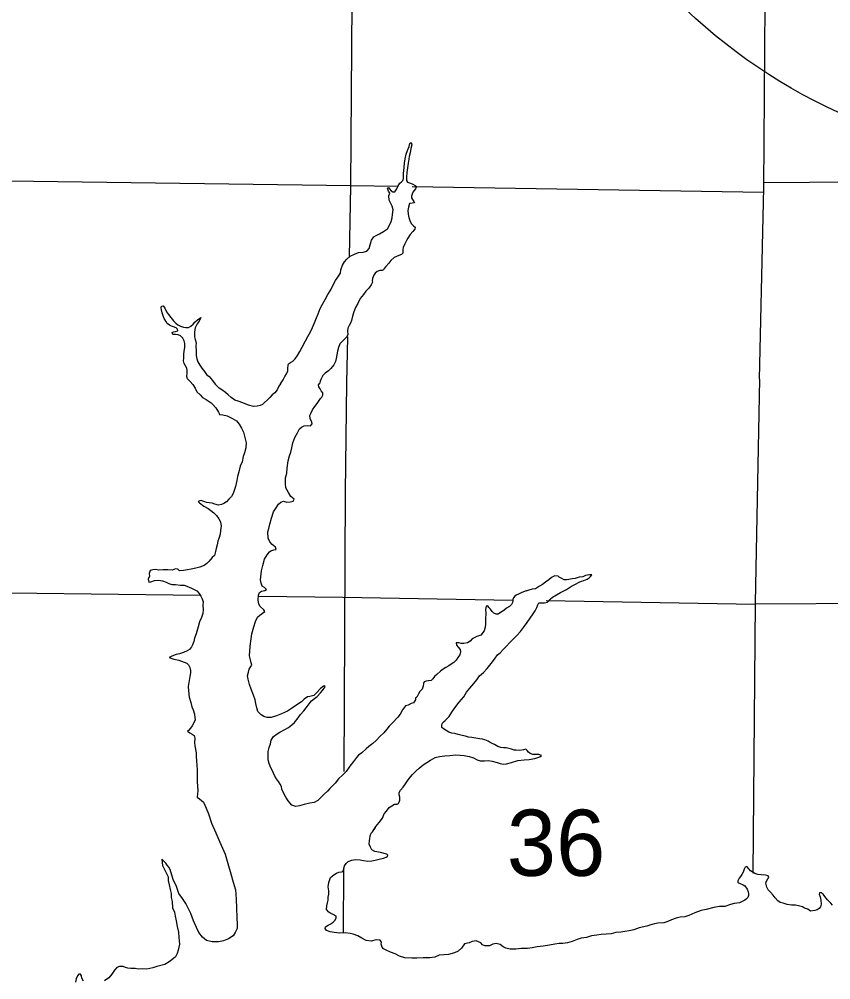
# Model space of a CAD drawing. Extents: x 77230 to 630905, y 790554 to 1662844.
# Drawn here: x 282531 to 292892, y 1585968 to 1598238 of the extents above; entities that cross this region are included whole.
import ezdxf

# ---------------------------------------------------------------- set-up
doc = ezdxf.new("R2010")
doc.units = 0
for name, color, linetype in [('Level 15', 7, 'Continuous'), ('Level 16', 7, 'Continuous'), ('Level 17', 7, 'Continuous'), ('Level 41', 7, 'Continuous')]:
    doc.layers.add(name, color=color, linetype=linetype)

msp = doc.modelspace()

# ---------------------------------------------------------------- linework, layer by layer
at = {"layer": 'Level 15'}
for points in [[(291982, 1593642), (292037, 1596088), (292076, 1601381), (292123, 1606664), (292223, 1611995), (292277, 1617183), (292295, 1618324)], [(291982, 1593642), (291925, 1590782), (291897, 1587331)]]:
    msp.add_lwpolyline(points, dxfattribs=at)
at = {"layer": 'Level 16'}
for points in [[(286981, 1617573), (286974, 1617268), (286950, 1611933), (286885, 1606684), (286800, 1601404), (286761, 1596105), (286743, 1595204)], [(267582, 1596443), (270927, 1596351), (276202, 1596266), (281460, 1596188), (286763, 1596113), (287364, 1596104)], [(292039, 1596154), (294372, 1596171)], [(287547, 1596101), (292034, 1596030)], [(286722, 1594182), (286711, 1593588)], [(286711, 1593588), (286693, 1592200), (286676, 1588627)], [(284846, 1590876), (281357, 1590920), (276135, 1591001), (276103, 1591002)], [(288831, 1590814), (286663, 1590853), (285588, 1590866)], [(291925, 1590760), (289256, 1590807)], [(291925, 1590806), (291929, 1590806)], [(291925, 1590770), (296585, 1590797), (298273, 1590778)], [(286671, 1587398), (286667, 1586565)]]:
    msp.add_lwpolyline(points, dxfattribs=at)
at = {"layer": 'Level 17'}
for points in [[(285866, 1593582), (285900, 1593632), (285923, 1593675), (285941, 1593707), (285959, 1593747), (285962, 1593781), (285964, 1593813), (285970, 1593837), (285992, 1593851), (286023, 1593870), (286053, 1593900), (286085, 1593944), (286114, 1593992), (286142, 1594047), (286187, 1594129), (286216, 1594187), (286248, 1594246), (286277, 1594302), (286301, 1594358), (286324, 1594423), (286348, 1594475), (286371, 1594543), (286399, 1594591), (286438, 1594658), (286471, 1594720), (286507, 1594780), (286540, 1594847), (286568, 1594899), (286599, 1594945), (286631, 1594996), (286638, 1595036), (286656, 1595098), (286683, 1595138), (286715, 1595174), (286755, 1595209), (286810, 1595237), (286864, 1595256), (286922, 1595264), (286970, 1595277), (286997, 1595311), (287011, 1595357), (287030, 1595417), (287058, 1595456), (287088, 1595476), (287129, 1595498), (287181, 1595527), (287231, 1595561), (287256, 1595609), (287278, 1595656), (287291, 1595700), (287297, 1595744), (287305, 1595802), (287294, 1595848), (287276, 1595884), (287254, 1595927), (287251, 1595980), (287263, 1596016), (287245, 1596041), (287232, 1596079), (287244, 1596087), (287260, 1596070), (287281, 1596044), (287301, 1596032), (287325, 1596032), (287352, 1596072), (287364, 1596103), (287389, 1596145), (287411, 1596161), (287429, 1596177), (287437, 1596205), (287438, 1596267), (287444, 1596343), (287451, 1596399), (287459, 1596456), (287472, 1596514), (287488, 1596562), (287507, 1596614), (287517, 1596650), (287535, 1596662), (287541, 1596632), (287531, 1596586), (287520, 1596532), (287508, 1596484), (287503, 1596450), (287497, 1596400), (287488, 1596340), (287480, 1596278), (287473, 1596222), (287475, 1596178), (287489, 1596156), (287527, 1596144), (287557, 1596132), (287587, 1596115), (287601, 1596099), (287590, 1596073), (287572, 1596052), (287556, 1596028), (287546, 1596004), (287537, 1595978), (287539, 1595956), (287553, 1595936)], [(287553, 1595936), (287567, 1595910), (287577, 1595894), (287547, 1595888), (287515, 1595884), (287502, 1595838), (287494, 1595796), (287495, 1595746), (287503, 1595704), (287519, 1595668), (287536, 1595630), (287566, 1595598), (287584, 1595580), (287582, 1595556), (287554, 1595528), (287521, 1595486), (287491, 1595441), (287474, 1595413), (287452, 1595369), (287434, 1595321), (287427, 1595295), (287429, 1595271), (287429, 1595251), (287411, 1595231), (287377, 1595218), (287346, 1595208), (287316, 1595192), (287276, 1595155), (287248, 1595123), (287211, 1595081), (287189, 1595054), (287181, 1595038), (287165, 1595026), (287135, 1595030), (287102, 1595014), (287076, 1594995), (287058, 1594967), (287040, 1594927), (287037, 1594897), (287039, 1594879), (287023, 1594847), (286994, 1594803), (286954, 1594766), (286926, 1594722), (286885, 1594670), (286852, 1594607), (286824, 1594555), (286803, 1594501), (286785, 1594445), (286772, 1594390), (286760, 1594354), (286742, 1594326), (286725, 1594292), (286723, 1594254), (286725, 1594210), (286715, 1594180), (286686, 1594156), (286656, 1594127), (286622, 1594091), (286605, 1594045), (286593, 1593997), (286584, 1593949), (286578, 1593905), (286570, 1593864), (286547, 1593824), (286509, 1593778), (286480, 1593746), (286438, 1593717), (286408, 1593685), (286385, 1593645), (286371, 1593615), (286367, 1593588)], [(284746, 1593572), (284712, 1593610), (284680, 1593644), (284672, 1593672), (284673, 1593716), (284673, 1593752), (284671, 1593782), (284653, 1593811), (284638, 1593841), (284630, 1593873), (284632, 1593907), (284631, 1593961), (284637, 1593999), (284643, 1594043), (284644, 1594094), (284636, 1594131), (284618, 1594163), (284591, 1594193), (284561, 1594207), (284527, 1594211), (284491, 1594210), (284485, 1594234), (284501, 1594246), (284525, 1594249), (284555, 1594257), (284551, 1594277), (284535, 1594297), (284501, 1594308), (284475, 1594316), (284448, 1594330), (284420, 1594352), (284404, 1594382), (284382, 1594413), (284370, 1594447), (284357, 1594489), (284349, 1594525), (284343, 1594551), (284349, 1594571), (284367, 1594575), (284391, 1594549), (284409, 1594502), (284435, 1594466), (284468, 1594426), (284500, 1594386), (284530, 1594357), (284556, 1594335), (284590, 1594317), (284628, 1594303), (284660, 1594300), (284690, 1594302), (284722, 1594316), (284750, 1594343), (284776, 1594373), (284805, 1594399), (284849, 1594427), (284829, 1594381), (284804, 1594345), (284776, 1594295), (284772, 1594275), (284767, 1594237), (284769, 1594179), (284777, 1594147), (284788, 1594105), (284786, 1594061), (284791, 1594005), (284791, 1593941), (284797, 1593901), (284812, 1593861), (284838, 1593819), (284862, 1593781), (284895, 1593738), (284923, 1593698), (284955, 1593674), (284977, 1593648), (284999, 1593622), (285032, 1593577)], [(284746, 1593572), (284775, 1593525), (284797, 1593477), (284839, 1593441), (284871, 1593407), (284917, 1593381), (284981, 1593339), (284999, 1593319), (285041, 1593273), (285055, 1593254), (285061, 1593238), (285075, 1593220), (285083, 1593202), (285087, 1593188), (285129, 1593184), (285185, 1593170), (285247, 1593140), (285305, 1593106), (285337, 1593067), (285369, 1593015), (285392, 1592965), (285410, 1592897), (285430, 1592825), (285426, 1592761), (285406, 1592697), (285390, 1592651), (285377, 1592585), (285353, 1592528), (285335, 1592456), (285319, 1592398), (285307, 1592346), (285292, 1592268), (285274, 1592216)], [(285866, 1593582), (285847, 1593549), (285823, 1593505), (285794, 1593465), (285760, 1593440), (285732, 1593406), (285700, 1593374), (285658, 1593336), (285638, 1593318), (285606, 1593302), (285568, 1593296), (285522, 1593293), (285458, 1593307), (285384, 1593337), (285326, 1593357), (285284, 1593372), (285236, 1593406), (285198, 1593442), (285164, 1593468), (285118, 1593502), (285084, 1593524), (285058, 1593550), (285032, 1593577)], [(285696, 1591395), (285726, 1591435), (285744, 1591449), (285780, 1591458), (285810, 1591464), (285801, 1591496), (285761, 1591528), (285731, 1591561), (285711, 1591611), (285703, 1591691), (285717, 1591733), (285731, 1591790), (285750, 1591864), (285778, 1591944), (285812, 1591998), (285842, 1592044), (285870, 1592068), (285904, 1592080), (285948, 1592071), (285992, 1592075), (286030, 1592081), (286039, 1592109), (285999, 1592143), (285967, 1592191), (285935, 1592253), (285931, 1592305), (285931, 1592379), (285947, 1592439), (285952, 1592503), (285966, 1592599), (285982, 1592661), (286000, 1592709), (286013, 1592763), (286025, 1592825), (286051, 1592897), (286083, 1592953), (286111, 1593004), (286135, 1593026), (286170, 1593044), (286216, 1593048), (286250, 1593044), (286270, 1593068), (286266, 1593090), (286246, 1593136), (286240, 1593176), (286256, 1593212), (286276, 1593250), (286306, 1593290), (286335, 1593329), (286379, 1593393), (286393, 1593411), (286407, 1593437), (286407, 1593467), (286387, 1593489), (286371, 1593515), (286357, 1593541), (286353, 1593569), (286367, 1593588)], [(285274, 1592216), (285262, 1592178), (285240, 1592140), (285208, 1592106), (285178, 1592074), (285145, 1592051), (285115, 1592039), (285075, 1592031), (285027, 1592043), (284993, 1592055), (284957, 1592059), (284923, 1592065), (284899, 1592074), (284877, 1592082), (284853, 1592092), (284835, 1592086), (284815, 1592078), (284833, 1592060), (284889, 1592016), (284941, 1591989), (284979, 1591963), (285017, 1591933), (285049, 1591899), (285079, 1591857), (285099, 1591817), (285109, 1591761), (285100, 1591707), (285098, 1591659), (285078, 1591605), (285066, 1591569), (285056, 1591523), (285044, 1591477), (285038, 1591437), (285023, 1591389), (284993, 1591361), (284955, 1591314), (284925, 1591286), (284891, 1591260), (284835, 1591238), (284787, 1591224), (284727, 1591211), (284678, 1591205), (284630, 1591195), (284578, 1591191), (284554, 1591211), (284526, 1591217), (284482, 1591200), (284426, 1591206), (284368, 1591204), (284310, 1591202), (284274, 1591208), (284236, 1591203), (284202, 1591197), (284190, 1591159), (284192, 1591125), (284178, 1591087), (284187, 1591045), (284213, 1591051), (284256, 1591068), (284308, 1591072), (284360, 1591062), (284406, 1591048), (284440, 1591028), (284478, 1591016), (284528, 1591017), (284588, 1591009), (284638, 1591009), (284694, 1590987), (284740, 1590965), (284800, 1590936), (284828, 1590902), (284850, 1590868), (284868, 1590836), (284881, 1590796), (284877, 1590752), (284879, 1590700), (284873, 1590646), (284857, 1590596), (284833, 1590542), (284814, 1590475), (284788, 1590387), (284768, 1590331), (284760, 1590291), (284742, 1590247), (284730, 1590219), (284703, 1590189), (284677, 1590169), (284629, 1590147), (284577, 1590132), (284533, 1590122), (284479, 1590102), (284445, 1590086), (284505, 1590064), (284567, 1590050), (284635, 1590027), (284669, 1590011), (284693, 1589993), (284709, 1589959), (284719, 1589919), (284717, 1589891), (284708, 1589843)], [(286109, 1588192), (286061, 1588181), (286013, 1588197), (285963, 1588255), (285933, 1588301), (285903, 1588355), (285885, 1588403), (285879, 1588435), (285864, 1588465), (285842, 1588499), (285816, 1588533), (285794, 1588569), (285778, 1588608), (285760, 1588644), (285738, 1588684), (285720, 1588732), (285708, 1588776), (285708, 1588830), (285709, 1588886), (285721, 1588934), (285739, 1588984), (285749, 1589029), (285777, 1589075), (285823, 1589109), (285860, 1589131), (285922, 1589165), (285968, 1589191), (286010, 1589224), (286044, 1589256), (286090, 1589314), (286122, 1589356), (286163, 1589402), (286195, 1589442), (286231, 1589495), (286261, 1589533), (286299, 1589561), (286335, 1589587), (286376, 1589633), (286402, 1589663), (286424, 1589693), (286436, 1589709), (286434, 1589725), (286414, 1589717), (286378, 1589687), (286328, 1589635), (286291, 1589599), (286243, 1589585), (286211, 1589583), (286167, 1589552), (286135, 1589518), (286075, 1589480), (286021, 1589442), (285954, 1589401), (285880, 1589367), (285814, 1589341), (285748, 1589317), (285696, 1589318), (285654, 1589332), (285618, 1589352), (285576, 1589394), (285564, 1589444), (285552, 1589496), (285542, 1589544), (285521, 1589604), (285491, 1589682), (285471, 1589742), (285453, 1589808), (285447, 1589850), (285457, 1589898), (285465, 1589934), (285486, 1589968), (285500, 1589986), (285492, 1590016), (285482, 1590054), (285470, 1590104), (285480, 1590230), (285493, 1590322), (285501, 1590386), (285527, 1590478), (285547, 1590544), (285574, 1590598), (285602, 1590625), (285638, 1590653), (285666, 1590671), (285654, 1590695), (285606, 1590737), (285590, 1590767), (285580, 1590823), (285584, 1590879), (285597, 1590913), (285625, 1590933), (285665, 1590939), (285687, 1590955), (285663, 1590979), (285633, 1590997), (285621, 1591033), (285611, 1591077), (285625, 1591191), (285640, 1591259), (285662, 1591339), (285696, 1591395)], [(288372, 1589801), (288406, 1589851), (288457, 1589893), (288503, 1589944), (288541, 1589988), (288573, 1590028), (288607, 1590078), (288637, 1590118), (288670, 1590146), (288708, 1590189), (288746, 1590225), (288794, 1590275), (288834, 1590313), (288882, 1590367), (288931, 1590418), (288969, 1590466), (289017, 1590530), (289055, 1590586), (289094, 1590642), (289118, 1590680), (289140, 1590722), (289152, 1590757), (289166, 1590781), (289200, 1590783), (289238, 1590783), (289276, 1590793), (289310, 1590829), (289340, 1590857), (289441, 1590914), (289519, 1590952), (289581, 1590998), (289633, 1591022), (289679, 1591045), (289709, 1591061), (289741, 1591069), (289782, 1591087), (289806, 1591103), (289826, 1591119), (289840, 1591139), (289810, 1591139), (289762, 1591133), (289726, 1591117), (289680, 1591111), (289629, 1591096), (289589, 1591088), (289549, 1591082), (289519, 1591076), (289489, 1591076), (289457, 1591096), (289425, 1591110), (289411, 1591124), (289367, 1591127), (289327, 1591107), (289293, 1591077), (289249, 1591047), (289213, 1591019), (289173, 1590995), (289149, 1590979), (289121, 1590964), (289078, 1590958), (289038, 1590946), (288998, 1590934)], [(288998, 1590934), (289004, 1590936), (288946, 1590916), (288904, 1590892), (288874, 1590883), (288856, 1590869), (288840, 1590847), (288832, 1590827), (288832, 1590809), (288830, 1590787), (288814, 1590761), (288789, 1590737), (288753, 1590713), (288717, 1590685), (288677, 1590661), (288647, 1590640), (288619, 1590640), (288591, 1590650), (288567, 1590674), (288547, 1590704), (288527, 1590722), (288515, 1590744), (288491, 1590742), (288485, 1590700), (288489, 1590646), (288483, 1590578), (288482, 1590512), (288478, 1590474), (288466, 1590424), (288424, 1590372), (288374, 1590351), (288338, 1590337), (288312, 1590325), (288288, 1590295), (288254, 1590271), (288205, 1590263), (288173, 1590264), (288143, 1590272), (288109, 1590272), (288113, 1590244), (288133, 1590218), (288159, 1590186), (288165, 1590156), (288155, 1590120), (288131, 1590086), (288107, 1590052), (288079, 1590022), (288046, 1589998), (288014, 1589980), (287976, 1589956), (287942, 1589937), (287908, 1589909), (287862, 1589869), (287832, 1589841), (287810, 1589813), (287788, 1589791), (287758, 1589787), (287727, 1589783), (287701, 1589776), (287693, 1589754), (287689, 1589720), (287673, 1589680), (287647, 1589650), (287629, 1589622), (287605, 1589580), (287589, 1589566), (287591, 1589542), (287564, 1589506), (287536, 1589496), (287498, 1589478), (287464, 1589469), (287426, 1589417), (287394, 1589363), (287364, 1589321), (287297, 1589251), (287253, 1589208), (287223, 1589170), (287187, 1589124), (287139, 1589078), (287087, 1589026), (287046, 1588988), (286996, 1588947), (286960, 1588917), (286904, 1588867), (286864, 1588837), (286838, 1588809), (286799, 1588757), (286753, 1588696), (286703, 1588630), (286663, 1588588), (286609, 1588534), (286564, 1588481), (286498, 1588413), (286468, 1588379), (286424, 1588339), (286378, 1588293), (286343, 1588259), (286297, 1588234), (286243, 1588224), (286169, 1588206), (286109, 1588192)], [(284708, 1589843), (284702, 1589793), (284688, 1589715), (284694, 1589661), (284702, 1589579), (284721, 1589511), (284735, 1589455), (284751, 1589415), (284769, 1589359), (284773, 1589317), (284775, 1589287), (284761, 1589249), (284739, 1589213), (284716, 1589183), (284690, 1589152), (284680, 1589142), (284708, 1589122), (284740, 1589107), (284764, 1589087), (284772, 1589055), (284768, 1588999), (284774, 1588955), (284788, 1588867), (284791, 1588819), (284793, 1588767), (284797, 1588705), (284803, 1588655), (284801, 1588601), (284803, 1588545), (284803, 1588495), (284806, 1588443), (284810, 1588385), (284806, 1588343), (284802, 1588301), (284832, 1588279), (284882, 1588235), (284916, 1588161), (284947, 1588087), (284987, 1587967), (285039, 1587847), (285091, 1587725), (285158, 1587572), (285194, 1587452), (285233, 1587322), (285263, 1587216), (285291, 1587118), (285299, 1586998), (285306, 1586882), (285310, 1586764), (285314, 1586674), (285313, 1586622), (285289, 1586572), (285263, 1586530), (285203, 1586493), (285137, 1586467), (285073, 1586453), (284995, 1586451), (284921, 1586472), (284869, 1586512), (284825, 1586572), (284795, 1586636), (284757, 1586720), (284721, 1586814), (284690, 1586876), (284658, 1586941), (284616, 1587007), (284568, 1587071), (284534, 1587173), (284502, 1587235), (284479, 1587303), (284459, 1587377), (284441, 1587407), (284419, 1587431), (284401, 1587459), (284353, 1587510), (284359, 1587430), (284399, 1587353), (284432, 1587285), (284434, 1587237), (284444, 1587181), (284456, 1587121), (284470, 1587069), (284472, 1587019), (284482, 1586969), (284487, 1586889)], [(287043, 1587859), (287085, 1587927), (287127, 1587977), (287168, 1588034), (287192, 1588090), (287218, 1588124), (287252, 1588168), (287286, 1588190), (287322, 1588210), (287354, 1588210), (287374, 1588221), (287383, 1588239), (287391, 1588263), (287389, 1588301), (287383, 1588329), (287381, 1588359), (287399, 1588389), (287431, 1588427), (287469, 1588485), (287497, 1588523), (287546, 1588585), (287594, 1588634), (287636, 1588672), (287686, 1588714), (287734, 1588742), (287783, 1588772), (287839, 1588809), (287897, 1588821), (287965, 1588827), (288027, 1588835), (288101, 1588842), (288161, 1588836), (288213, 1588832), (288275, 1588822), (288331, 1588805), (288377, 1588779), (288417, 1588763), (288471, 1588763), (288521, 1588771), (288567, 1588759), (288631, 1588742), (288669, 1588730), (288713, 1588722), (288753, 1588726), (288814, 1588744), (288896, 1588771), (288978, 1588779), (289042, 1588781), (289112, 1588794), (289150, 1588808), (289178, 1588814), (289200, 1588832), (289166, 1588844), (289120, 1588846), (289086, 1588845), (289052, 1588857), (289034, 1588875), (289014, 1588895), (288998, 1588913), (288968, 1588905), (288920, 1588899), (288876, 1588903), (288848, 1588903), (288816, 1588912), (288782, 1588924), (288748, 1588930), (288712, 1588932), (288678, 1588936), (288642, 1588950), (288598, 1588972), (288570, 1588988), (288544, 1589001), (288516, 1589017), (288474, 1589035), (288444, 1589041), (288406, 1589045), (288360, 1589053), (288308, 1589065), (288268, 1589068), (288230, 1589080), (288186, 1589090), (288134, 1589102), (288094, 1589112), (288052, 1589118), (288014, 1589129), (287980, 1589153), (287948, 1589175), (287928, 1589191), (287924, 1589227), (287940, 1589255), (287968, 1589281), (287994, 1589307), (288018, 1589333), (288055, 1589386), (288091, 1589444), (288149, 1589514), (288205, 1589584), (288242, 1589640), (288282, 1589691), (288336, 1589751), (288372, 1589801)], [(288670, 1586417), (288618, 1586431), (288578, 1586422), (288534, 1586402), (288474, 1586400), (288444, 1586416), (288422, 1586442), (288366, 1586466), (288312, 1586459), (288274, 1586439), (288216, 1586429), (288176, 1586371), (288134, 1586333), (288088, 1586311), (288011, 1586290), (287955, 1586286), (287893, 1586282), (287835, 1586256), (287773, 1586249), (287689, 1586249), (287609, 1586245), (287541, 1586246), (287453, 1586248), (287387, 1586270), (287329, 1586298), (287271, 1586321), (287215, 1586345), (287183, 1586365), (287163, 1586387), (287153, 1586423), (287157, 1586447), (287139, 1586473), (287089, 1586477), (287023, 1586460), (286961, 1586468), (286905, 1586498), (286855, 1586530), (286793, 1586552), (286757, 1586561), (286693, 1586567), (286619, 1586565), (286553, 1586571), (286501, 1586580), (286453, 1586596), (286435, 1586624), (286439, 1586646), (286477, 1586668), (286501, 1586678), (286537, 1586703), (286561, 1586725), (286577, 1586755), (286579, 1586779), (286537, 1586801), (286511, 1586815), (286483, 1586834), (286455, 1586868), (286460, 1586914), (286468, 1586950), (286476, 1586985), (286476, 1587025), (286482, 1587061), (286482, 1587105), (286474, 1587155), (286482, 1587211), (286497, 1587251), (286505, 1587275), (286549, 1587307), (286581, 1587329), (286611, 1587341), (286645, 1587349), (286663, 1587353), (286673, 1587383), (286685, 1587422), (286703, 1587454), (286732, 1587480), (286778, 1587498), (286820, 1587504), (286882, 1587500), (286926, 1587490), (286982, 1587485), (287034, 1587489), (287074, 1587495), (287128, 1587511), (287180, 1587523), (287230, 1587540), (287238, 1587558), (287222, 1587572), (287142, 1587593), (287070, 1587607), (287034, 1587627), (287014, 1587661), (286999, 1587701), (287001, 1587745), (287007, 1587773), (287011, 1587809), (287025, 1587839), (287043, 1587859), (287081, 1587913)], [(292760, 1586899), (292742, 1586877), (292716, 1586861), (292688, 1586855), (292634, 1586846), (292598, 1586870), (292558, 1586884), (292530, 1586902), (292480, 1586914), (292440, 1586922), (292392, 1586922), (292334, 1586931), (292282, 1586949), (292244, 1586957), (292216, 1586977), (292182, 1587015), (292156, 1587047), (292124, 1587087), (292094, 1587118), (292074, 1587152), (292062, 1587204), (292071, 1587230), (292089, 1587257), (292099, 1587275), (292091, 1587297), (292057, 1587306), (292001, 1587308), (291959, 1587312), (291921, 1587326), (291867, 1587360), (291845, 1587384), (291821, 1587414), (291799, 1587405), (291785, 1587381), (291775, 1587345), (291758, 1587311), (291738, 1587287), (291724, 1587267), (291706, 1587233), (291706, 1587213), (291736, 1587199), (291772, 1587181), (291796, 1587169), (291826, 1587125), (291836, 1587091), (291842, 1587065), (291840, 1587043), (291834, 1587021), (291816, 1587001), (291794, 1586985), (291725, 1586953), (291659, 1586943), (291613, 1586931), (291537, 1586906), (291471, 1586904), (291397, 1586892), (291299, 1586867), (291235, 1586855), (291158, 1586823), (291080, 1586788), (291028, 1586772), (290968, 1586768), (290916, 1586754), (290860, 1586732), (290810, 1586713), (290760, 1586697), (290685, 1586691), (290643, 1586685), (290583, 1586666), (290545, 1586652), (290447, 1586630), (290377, 1586608), (290317, 1586593), (290261, 1586585), (290213, 1586577), (290149, 1586573), (290088, 1586554), (290024, 1586552), (289960, 1586546), (289904, 1586538), (289838, 1586529), (289774, 1586509), (289704, 1586499), (289652, 1586483), (289592, 1586458), (289531, 1586440), (289469, 1586432), (289423, 1586430), (289367, 1586422), (289299, 1586411), (289219, 1586397), (289145, 1586391), (289079, 1586376), (289019, 1586368), (288939, 1586366), (288871, 1586360), (288798, 1586361), (288742, 1586371), (288734, 1586377), (288710, 1586391), (288670, 1586417)], [(292913, 1586922), (292891, 1586948), (292851, 1586989), (292817, 1587033), (292793, 1587063), (292767, 1587081), (292749, 1587081), (292745, 1587063), (292755, 1587027), (292765, 1586987), (292768, 1586933), (292760, 1586899)], [(284487, 1586889), (284513, 1586833), (284521, 1586781), (284535, 1586723), (284549, 1586649), (284565, 1586577), (284568, 1586507), (284576, 1586425), (284562, 1586347), (284548, 1586305), (284526, 1586263), (284481, 1586222), (284443, 1586196), (284389, 1586162), (284339, 1586152), (284287, 1586136), (284235, 1586119), (284159, 1586103), (284101, 1586107), (284049, 1586105), (284011, 1586111), (283956, 1586112), (283916, 1586118), (283886, 1586126), (283856, 1586138), (283812, 1586140), (283776, 1586126), (283748, 1586090), (283712, 1586041), (283674, 1585993), (283618, 1585953)], [(283353, 1585952), (283331, 1585990), (283326, 1586020), (283312, 1586042), (283292, 1586040), (283275, 1586018), (283259, 1585980), (283249, 1585937)]]:
    msp.add_lwpolyline(points, dxfattribs=at)
at = {"layer": 'Level 41'}
msp.add_circle((295872, 1603429), 7000, dxfattribs=at)

# ---------------------------------------------------------------- texts
at = {"layer": 'Level 16'}
msp.add_text('36', height=844.8, dxfattribs=at).set_placement((288756, 1587296))

doc.saveas('drawing.dxf')
